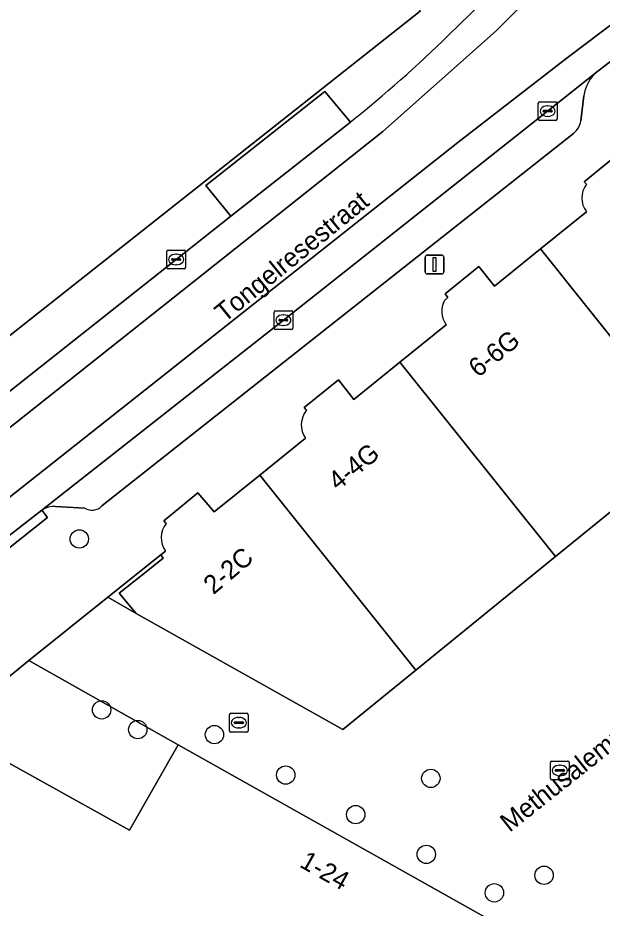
# Model space of a CAD drawing. Extents: x 161771 to 163125, y 382475 to 383179.
# Drawn here: x 161929.62 to 161960.76, y 382847.18 to 382894.58 of the extents above; entities that cross this region are included whole.
import ezdxf

# ---------------------------------------------------------------- set-up
doc = ezdxf.new("R2010")
doc.units = 0
for name, color, linetype in [('IMGEO_Boom', 7, 'Continuous'), ('IMGEO_Erf', 7, 'Continuous'), ('IMGEO_Kolk', 7, 'Continuous'), ('IMGEO_Lichtmast', 7, 'Continuous'), ('IMGEO_Openbare_ruimte_label', 7, 'Continuous'), ('IMGEO_Pand', 7, 'Continuous'), ('IMGEO_Pand_nummerreeks', 7, 'Continuous'), ('IMGEO_Parkeervlak_open', 7, 'Continuous'), ('IMGEO_Rijbaan_lokaal_gesloten', 7, 'Continuous'), ('IMGEO_Rijbaan_lokaal_open', 7, 'Continuous'), ('IMGEO_Voetpad_open', 7, 'Continuous')]:
    doc.layers.add(name, color=color, linetype=linetype)

msp = doc.modelspace()

# ---------------------------------------------------------------- linework, layer by layer
at = {"layer": 'IMGEO_Boom'}
for centre in [(161932.898, 382866.837), (161934.089, 382857.74), (161936.016, 382856.692), (161940.101, 382856.42), (161943.897, 382854.272), (161951.627, 382854.094), (161947.625, 382852.162), (161951.387, 382850.048), (161957.662, 382848.932), (161955.014, 382848)]:
    msp.add_circle(centre, 0.489, dxfattribs=at)
at = {"layer": 'IMGEO_Erf'}
msp.add_lwpolyline([(161900.894, 382876.985), (161901.529, 382877.193), (161905.412, 382882.906), (161905.712, 382882.691), (161905.624, 382882.569), (161911.455, 382878.382), (161911.769, 382878.595), (161914.467, 382880.423), (161916.877, 382882.056), (161917.176, 382881.615), (161919.981, 382877.476), (161911.69, 382871.858), (161906.895, 382868.609), (161905.911, 382867.987), (161906.823, 382866.741), (161909.943, 382862.484), (161951.054, 382894.925), (161948.535, 382900.058), (161975.504, 382921.534)], dxfattribs=at)
msp.add_lwpolyline([(161925.788, 382856.766), (161935.571, 382851.327), (161938.172, 382855.87), (161930.217, 382860.359)], close=True, dxfattribs=at)
at = {"layer": 'IMGEO_Kolk'}
for p, q in [((161957.35, 382889.188), (161957.35, 382890.04)), ((161957.425, 382890.114), (161958.277, 382890.114)), ((161958.351, 382890.04), (161958.351, 382889.188)), ((161957.609, 382889.608), (161957.609, 382889.62)), ((161958.047, 382889.571), (161957.649, 382889.571)), ((161957.652, 382889.657), (161958.05, 382889.657)), ((161957.838, 382889.894), (161957.863, 382889.894)), ((161958.093, 382889.62), (161958.093, 382889.608)), ((161958.277, 382889.114), (161957.425, 382889.114)), ((161957.861, 382889.334), (161957.836, 382889.334)), ((161937.558, 382881.287), (161937.558, 382882.139)), ((161937.633, 382882.213), (161938.485, 382882.213)), ((161938.046, 382881.993), (161938.071, 382881.993)), ((161938.559, 382882.139), (161938.559, 382881.287)), ((161937.817, 382881.707), (161937.817, 382881.719)), ((161938.255, 382881.67), (161937.857, 382881.67)), ((161937.86, 382881.756), (161938.258, 382881.756)), ((161938.301, 382881.719), (161938.301, 382881.707)), ((161938.485, 382881.213), (161937.633, 382881.213)), ((161938.069, 382881.433), (161938.044, 382881.433)), ((161943.272, 382878.058), (161943.272, 382878.91)), ((161943.347, 382878.984), (161944.199, 382878.984)), ((161943.76, 382878.764), (161943.785, 382878.764)), ((161944.273, 382878.91), (161944.273, 382878.058)), ((161943.531, 382878.478), (161943.531, 382878.49)), ((161943.969, 382878.441), (161943.571, 382878.441)), ((161943.574, 382878.527), (161943.972, 382878.527)), ((161943.783, 382878.204), (161943.758, 382878.204)), ((161944.015, 382878.49), (161944.015, 382878.478)), ((161944.199, 382877.984), (161943.347, 382877.984)), ((161940.898, 382856.63), (161940.898, 382857.482)), ((161940.973, 382857.556), (161941.825, 382857.556)), ((161941.386, 382857.336), (161941.411, 382857.336)), ((161941.899, 382857.482), (161941.899, 382856.63)), ((161941.157, 382857.05), (161941.157, 382857.062)), ((161941.595, 382857.013), (161941.197, 382857.013)), ((161941.2, 382857.099), (161941.598, 382857.099)), ((161941.641, 382857.062), (161941.641, 382857.05)), ((161941.825, 382856.556), (161940.973, 382856.556)), ((161941.409, 382856.776), (161941.384, 382856.776)), ((161958.074, 382855.015), (161958.926, 382855.015)), ((161957.999, 382854.089), (161957.999, 382854.941)), ((161958.258, 382854.509), (161958.258, 382854.521)), ((161958.301, 382854.558), (161958.699, 382854.558)), ((161958.487, 382854.795), (161958.512, 382854.795)), ((161958.742, 382854.521), (161958.742, 382854.509)), ((161959, 382854.941), (161959, 382854.089)), ((161958.926, 382854.015), (161958.074, 382854.015)), ((161958.696, 382854.472), (161958.298, 382854.472)), ((161958.51, 382854.235), (161958.485, 382854.235))]:
    msp.add_line(p, q, dxfattribs=at)
for points in [[(161957.35, 382889.188), (161957.35, 382890.04)], [(161957.425, 382890.114), (161958.277, 382890.114)], [(161958.351, 382890.04), (161958.351, 382889.188)], [(161958.277, 382889.114), (161957.425, 382889.114)], [(161937.558, 382881.287), (161937.558, 382882.139)], [(161937.633, 382882.213), (161938.485, 382882.213)], [(161938.559, 382882.139), (161938.559, 382881.287)], [(161938.485, 382881.213), (161937.633, 382881.213)], [(161943.272, 382878.058), (161943.272, 382878.91)], [(161943.347, 382878.984), (161944.199, 382878.984)], [(161944.273, 382878.91), (161944.273, 382878.058)], [(161944.199, 382877.984), (161943.347, 382877.984)], [(161940.898, 382856.63), (161940.898, 382857.482)], [(161940.973, 382857.556), (161941.825, 382857.556)], [(161941.899, 382857.482), (161941.899, 382856.63)], [(161941.825, 382856.556), (161940.973, 382856.556)], [(161958.074, 382855.015), (161958.926, 382855.015)], [(161957.999, 382854.089), (161957.999, 382854.941)], [(161959, 382854.941), (161959, 382854.089)], [(161958.926, 382854.015), (161958.074, 382854.015)]]:
    msp.add_lwpolyline(points, dxfattribs=at)
for centre, radius, start, end in [((161957.427, 382890.038), 0.0765, 91.552, 178.448), ((161957.427, 382890.038), 0.0765, 91.552, 178.448), ((161958.275, 382890.038), 0.0765, 1.552, 88.448), ((161958.275, 382890.038), 0.0765, 1.552, 88.448), ((161957.649, 382889.617), 0.0403, 85.8775, 175.7526), ((161957.646, 382889.607), 0.0366, 178.938, 274.7102), ((161958.05, 382889.614), 0.043, 264.8664, 352.4533), ((161958.054, 382889.619), 0.0386, 1.7309, 96.639), ((161957.427, 382889.19), 0.0765, 181.552, 268.448), ((161957.427, 382889.19), 0.0765, 181.552, 268.448), ((161958.275, 382889.19), 0.0765, 271.552, 358.448), ((161958.275, 382889.19), 0.0765, 271.552, 358.448), ((161937.635, 382882.137), 0.0765, 91.552, 178.448), ((161937.635, 382882.137), 0.0765, 91.552, 178.448), ((161938.483, 382882.137), 0.0765, 1.552, 88.448), ((161938.483, 382882.137), 0.0765, 1.552, 88.448), ((161937.857, 382881.716), 0.0403, 85.8775, 175.7526), ((161937.854, 382881.706), 0.0366, 178.938, 274.7102), ((161938.258, 382881.713), 0.043, 264.8664, 352.4533), ((161938.262, 382881.718), 0.0386, 1.7309, 96.639), ((161937.635, 382881.289), 0.0765, 181.552, 268.448), ((161937.635, 382881.289), 0.0765, 181.552, 268.448), ((161938.483, 382881.289), 0.0765, 271.552, 358.448), ((161938.483, 382881.289), 0.0765, 271.552, 358.448), ((161943.349, 382878.908), 0.0765, 91.552, 178.448), ((161943.349, 382878.908), 0.0765, 91.552, 178.448), ((161944.197, 382878.908), 0.0765, 1.552, 88.448), ((161944.197, 382878.908), 0.0765, 1.552, 88.448), ((161943.571, 382878.487), 0.0403, 85.8775, 175.7526), ((161943.568, 382878.477), 0.0366, 178.938, 274.7102), ((161943.972, 382878.484), 0.043, 264.8664, 352.4533), ((161943.976, 382878.489), 0.0386, 1.7309, 96.639), ((161943.349, 382878.06), 0.0765, 181.552, 268.448), ((161943.349, 382878.06), 0.0765, 181.552, 268.448), ((161944.197, 382878.06), 0.0765, 271.552, 358.448), ((161944.197, 382878.06), 0.0765, 271.552, 358.448), ((161940.975, 382857.48), 0.0765, 91.552, 178.448), ((161940.975, 382857.48), 0.0765, 91.552, 178.448), ((161941.823, 382857.48), 0.0765, 1.552, 88.448), ((161941.823, 382857.48), 0.0765, 1.552, 88.448), ((161941.197, 382857.059), 0.0403, 85.8775, 175.7526), ((161941.194, 382857.049), 0.0366, 178.938, 274.7102), ((161941.598, 382857.056), 0.043, 264.8664, 352.4533), ((161941.602, 382857.061), 0.0386, 1.7309, 96.639), ((161940.975, 382856.632), 0.0765, 181.552, 268.448), ((161940.975, 382856.632), 0.0765, 181.552, 268.448), ((161941.823, 382856.632), 0.0765, 271.552, 358.448), ((161941.823, 382856.632), 0.0765, 271.552, 358.448), ((161958.076, 382854.939), 0.0765, 91.552, 178.448), ((161958.076, 382854.939), 0.0765, 91.552, 178.448), ((161958.924, 382854.939), 0.0765, 1.552, 88.448), ((161958.924, 382854.939), 0.0765, 1.552, 88.448), ((161958.298, 382854.518), 0.0403, 85.8775, 175.7526), ((161958.295, 382854.508), 0.0366, 178.938, 274.7102), ((161958.699, 382854.515), 0.043, 264.8664, 352.4533), ((161958.703, 382854.52), 0.0386, 1.7309, 96.639), ((161958.076, 382854.091), 0.0765, 181.552, 268.448), ((161958.076, 382854.091), 0.0765, 181.552, 268.448), ((161958.924, 382854.091), 0.0765, 271.552, 358.448), ((161958.924, 382854.091), 0.0765, 271.552, 358.448)]:
    msp.add_arc(centre, radius, start, end, dxfattribs=at)
for centre, major_axis, ratio, start_param, end_param in [((161957.837, 382889.614), (-0.387, 0.002), 0.722429, 4.712389, 7.853982), ((161957.862, 382889.614), (-0.39, 0.002), 0.717154, 1.570796, 4.712389), ((161938.045, 382881.713), (-0.387, 0.002), 0.722429, 4.712389, 7.853982), ((161938.07, 382881.713), (-0.39, 0.002), 0.717154, 1.570796, 4.712389), ((161943.759, 382878.484), (-0.387, 0.002), 0.722429, 4.712389, 7.853982), ((161943.784, 382878.484), (-0.39, 0.002), 0.717154, 1.570796, 4.712389), ((161941.385, 382857.056), (-0.387, 0.002), 0.722429, 4.712389, 7.853982), ((161941.41, 382857.056), (-0.39, 0.002), 0.717154, 1.570796, 4.712389), ((161958.486, 382854.515), (-0.387, 0.002), 0.722429, 4.712389, 7.853982), ((161958.511, 382854.515), (-0.39, 0.002), 0.717154, 1.570796, 4.712389)]:
    msp.add_ellipse(centre, major_axis=major_axis, ratio=ratio, start_param=start_param, end_param=end_param, dxfattribs=at)
at = {"layer": 'IMGEO_Lichtmast'}
for p, q in [((161951.328, 382881.046), (161951.328, 382881.846)), ((161951.328, 382881.846), (161951.328, 382881.046)), ((161951.428, 382881.946), (161952.218, 382881.946)), ((161952.218, 382881.946), (161951.428, 382881.946)), ((161952.318, 382881.846), (161952.318, 382881.046)), ((161952.318, 382881.046), (161952.318, 382881.846)), ((161952.218, 382880.946), (161951.428, 382880.946)), ((161951.428, 382880.946), (161952.218, 382880.946))]:
    msp.add_line(p, q, dxfattribs=at)
msp.add_lwpolyline([(161951.748, 382881.821), (161951.898, 382881.821), (161951.898, 382881.071), (161951.748, 382881.071), (161951.748, 382881.821)], dxfattribs=at)
for centre, start, end in [((161951.428, 382881.846), 90, 180), ((161951.428, 382881.846), 90, 180), ((161952.218, 382881.846), 0, 90), ((161952.218, 382881.846), 360, 90), ((161951.428, 382881.046), 180, 270), ((161951.428, 382881.046), 180, 270), ((161952.218, 382881.046), 270, 0), ((161952.218, 382881.046), 270, 0)]:
    msp.add_arc(centre, 0.1, start, end, dxfattribs=at)
at = {"layer": 'IMGEO_Pand'}
for points in [[(161959.925, 382884.258), (161957.469, 382882.28), (161965.723, 382871.957), (161972.904, 382877.793), (161964.644, 382888.061), (161962.479, 382886.318), (161961.638, 382887.364), (161959.802, 382885.85), (161959.921, 382885.716)], [(161952.439, 382878.242), (161949.981, 382876.255), (161958.264, 382865.896), (161965.723, 382871.957), (161957.469, 382882.28), (161955.013, 382880.302), (161954.178, 382881.333), (161952.383, 382879.881), (161952.536, 382879.692), (161952.363, 382879.535)], [(161944.949, 382872.202), (161942.513, 382870.237), (161950.82, 382859.847), (161958.264, 382865.896), (161949.981, 382876.255), (161947.523, 382874.268), (161946.7, 382875.316), (161944.875, 382873.839), (161944.997, 382873.687)], [(161937.488, 382866.185), (161937.25, 382865.994), (161937.361, 382865.818), (161936.542, 382865.165), (161935.018, 382863.95), (161935.925, 382862.875), (161946.938, 382856.692), (161950.82, 382859.847), (161942.513, 382870.237)], [(161942.513, 382870.237), (161940.077, 382868.273), (161939.209, 382869.301), (161937.396, 382867.801), (161937.532, 382867.669)]]:
    msp.add_lwpolyline(points, dxfattribs=at)
msp.add_lwpolyline([(161938.172, 382855.87), (161935.571, 382851.327), (161925.788, 382856.766), (161923.225, 382854.706), (161921.507, 382853.326), (161918.6, 382851.014), (161914.919, 382848.172), (161915.064, 382843.832), (161919.34, 382841.346), (161919.878, 382842.285), (161944.451, 382828.498), (161949.455, 382837.351), (161954.479, 382841.299), (161958.508, 382844.465)], close=True, dxfattribs=at)
for centre, radius, start, end in [((161960.842, 382884.99), 1.173, 141.7381, 218.5763), ((161953.4, 382878.947), 1.192, 150.4431, 216.2847), ((161945.96, 382872.913), 1.236, 141.2071, 215.0902), ((161938.516, 382866.897), 1.251, 141.8967, 214.7067)]:
    msp.add_arc(centre, radius, start, end, dxfattribs=at)
at = {"layer": 'IMGEO_Parkeervlak_open'}
for points in [[(161960.518, 382891.736), (161957.85, 382889.615), (161943.772, 382878.485), (161930.903, 382868.365)], [(161959.623, 382889.091), (161959.773, 382890.423)], [(161934.101, 382868.596), (161959.23, 382888.42)], [(161931.638, 382868.566), (161933.186, 382868.485)]]:
    msp.add_lwpolyline(points, dxfattribs=at)
for centre, radius, start, end in [((161961.832, 382890.122), 2.081, 129.163, 171.6956), ((161958.508, 382889.294), 1.133, 309.5798, 349.7058), ((161931.539, 382867.485), 1.086, 84.7569, 125.8325), ((161933.576, 382869.095), 0.724, 237.3755, 316.4582)]:
    msp.add_arc(centre, radius, start, end, dxfattribs=at)
at = {"layer": 'IMGEO_Rijbaan_lokaal_gesloten'}
for points in [[(162164.558, 383059.775), (162164.975, 383060.328), (162165.507, 383060.724), (162166.652, 383061.481), (162166.023, 383061.618), (162164.197, 383062.015), (162160.98, 383057.918), (162135.752, 383036.849), (162098.092, 383005.831), (162064.893, 382976.459), (162028.312, 382947.355), (161996.833, 382921.662), (161989.309, 382915.625), (161975.267, 382904.355), (161969.513, 382899.968), (161964.685, 382896.828), (161958.891, 382892.441), (161953.057, 382887.933), (161929.84, 382869.578), (161924.324, 382865.246), (161911.803, 382855.192)], [(161911.803, 382855.192), (161924.324, 382865.246), (161929.84, 382869.578), (161953.057, 382887.933), (161958.891, 382892.441), (161964.685, 382896.828), (161969.513, 382899.968), (161975.267, 382904.355), (161989.309, 382915.625), (161996.833, 382921.662), (162028.312, 382947.355), (162064.893, 382976.459)], [(161990.16, 382924.643), (161976.155, 382915.855), (161975.569, 382915.367), (161972.262, 382912.726), (161972.061, 382912.573), (161969.002, 382909.781), (161961.466, 382902.382), (161954.9, 382895.919), (161952.577, 382893.655)], [(161971.782, 382910.311), (161968.91, 382907.575), (161962.673, 382901.457), (161955.109, 382893.89), (161949.073, 382888.536), (161927.185, 382871.189), (161922.252, 382867.375), (161908.45, 382856.623)], [(161949.073, 382888.536), (161955.109, 382893.89), (161962.673, 382901.457), (161968.91, 382907.575), (161971.782, 382910.311)], [(161912.17, 382853.617), (161913.232, 382854.443), (161921.638, 382861.112), (161924.047, 382863.024), (161924.544, 382863.419), (161926.098, 382864.645), (161930.903, 382868.365), (161943.772, 382878.485), (161957.85, 382889.615), (161960.518, 382891.736), (161963.693, 382894.145)], [(161947.342, 382889.033), (161940.977, 382884.015), (161938.06, 382881.713), (161927.91, 382873.689), (161923.524, 382870.207), (161922.09, 382869.147), (161920.363, 382867.779), (161906.632, 382857.001)], [(161908.45, 382856.623), (161922.252, 382867.375), (161927.185, 382871.189), (161949.073, 382888.536)]]:
    msp.add_lwpolyline(points, dxfattribs=at)
msp.add_arc((161905.336, 382941.886), 67.512, 308.47676, 314.40604, dxfattribs=at)
at = {"layer": 'IMGEO_Rijbaan_lokaal_open'}
msp.add_lwpolyline([(161965.723, 382871.957), (161958.264, 382865.896), (161950.82, 382859.847), (161946.938, 382856.692), (161935.925, 382862.875), (161934.42, 382863.739), (161930.217, 382860.359), (161938.172, 382855.87), (161958.508, 382844.465), (161960.405, 382846.092), (161968.728, 382852.865)], dxfattribs=at)
at = {"layer": 'IMGEO_Voetpad_open'}
for points in [[(161978.838, 382923.678), (161975.504, 382921.534), (161948.535, 382900.058), (161951.054, 382894.925), (161909.943, 382862.484), (161902.967, 382857.371), (161901.316, 382856.161), (161903.978, 382854.245)], [(161952.577, 382893.655), (161954.9, 382895.919), (161961.466, 382902.382), (161961.105, 382902.755), (161968.654, 382910.147), (161969.002, 382909.781), (161972.061, 382912.573), (161972.262, 382912.726), (161975.569, 382915.367), (161976.155, 382915.855), (161976.721, 382916.411)], [(161963.693, 382894.145), (161960.518, 382891.736)], [(161922.219, 382871.86), (161926.671, 382875.315), (161927.91, 382873.689), (161938.06, 382881.713), (161940.977, 382884.015), (161939.632, 382885.646), (161945.975, 382890.663), (161947.342, 382889.033)], [(161959.773, 382890.423), (161959.623, 382889.091)], [(161959.23, 382888.42), (161934.101, 382868.596)], [(161959.921, 382885.716), (161959.802, 382885.85), (161961.638, 382887.364)], [(161952.363, 382879.535), (161952.536, 382879.692), (161952.383, 382879.881), (161954.178, 382881.333), (161955.013, 382880.302), (161957.469, 382882.28), (161959.925, 382884.258)], [(161944.997, 382873.687), (161944.875, 382873.839), (161946.7, 382875.316), (161947.523, 382874.268), (161949.981, 382876.255), (161952.439, 382878.242)], [(161937.532, 382867.669), (161937.396, 382867.801), (161939.209, 382869.301), (161940.077, 382868.273), (161942.513, 382870.237), (161944.949, 382872.202)], [(161930.903, 382868.365), (161931.212, 382867.973), (161924.948, 382863.033), (161924.544, 382863.419), (161924.047, 382863.024), (161921.638, 382861.112)], [(161933.186, 382868.485), (161931.638, 382868.566)], [(161908.806, 382849.443), (161908.423, 382848.544), (161915.064, 382843.832), (161914.919, 382848.172), (161918.6, 382851.014), (161919.975, 382853.379), (161920.916, 382852.897), (161922.304, 382855.223), (161923.225, 382854.706), (161925.788, 382856.766), (161930.217, 382860.359), (161934.42, 382863.739), (161937.25, 382865.994), (161937.488, 382866.185)]]:
    msp.add_lwpolyline(points, dxfattribs=at)
for points in [[(161940.977, 382884.015), (161947.342, 382889.033), (161945.975, 382890.663), (161939.632, 382885.646)], [(161931.212, 382867.973), (161930.903, 382868.365), (161926.098, 382864.645), (161924.544, 382863.419), (161924.948, 382863.033)], [(161936.542, 382865.165), (161937.361, 382865.818), (161937.25, 382865.994), (161934.42, 382863.739), (161935.925, 382862.875), (161935.018, 382863.95)]]:
    msp.add_lwpolyline(points, close=True, dxfattribs=at)
for centre, radius, start, end in [((161905.336, 382941.886), 67.512, 308.47676, 314.40604), ((161961.832, 382890.122), 2.081, 129.163, 171.6956), ((161958.508, 382889.294), 1.133, 309.5798, 349.7058), ((161960.842, 382884.99), 1.173, 141.7381, 218.5763), ((161953.4, 382878.947), 1.192, 150.4431, 216.2847), ((161945.96, 382872.913), 1.236, 141.2071, 215.0902), ((161931.539, 382867.485), 1.086, 84.7569, 125.8325), ((161933.576, 382869.095), 0.724, 237.3755, 316.4582), ((161938.516, 382866.897), 1.251, 141.8967, 214.7067)]:
    msp.add_arc(centre, radius, start, end, dxfattribs=at)

# ---------------------------------------------------------------- texts
at = {"layer": 'IMGEO_Openbare_ruimte_label'}
for s, rotation, p in [('Tongelresestraat', 39.1161, (161940.634, 382878.328)), ('Methusalemplein', 38.4629, (161955.824, 382851.191))]:
    msp.add_text(s, height=1, rotation=rotation, dxfattribs=at).set_placement(p)
at = {"layer": 'IMGEO_Pand_nummerreeks'}
for s, rotation, p in [('6-6G', 38.8209, (161954.146, 382875.396)), ('4-4G', 38.8609, (161946.67, 382869.375)), ('2-2C', 40.3477, (161940.048, 382863.84)), ('1-24', 330.7161, (161944.574, 382849.413))]:
    msp.add_text(s, height=1, rotation=rotation, dxfattribs=at).set_placement(p)

doc.saveas('drawing.dxf')
